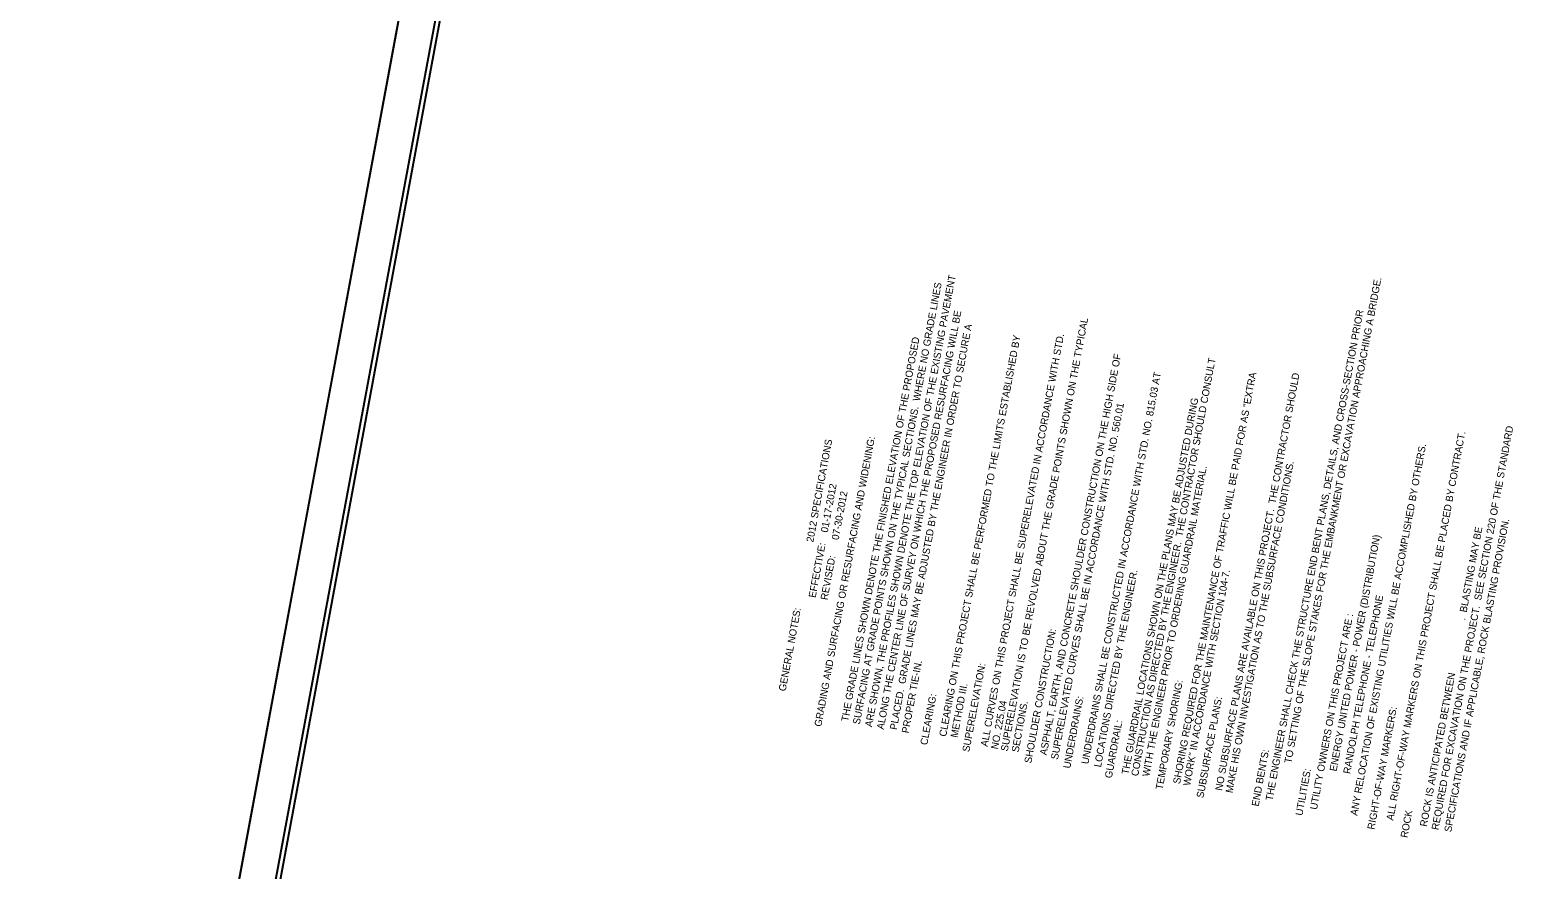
# Model space of a CAD drawing. Extents: x 1665923 to 1668724, y 690926 to 694920.
# Drawn here: x 1667341 to 1668177, y 693895 to 694361 of the extents above; entities that cross this region are included whole.
import ezdxf

# ---------------------------------------------------------------- set-up
doc = ezdxf.new("R2010")
doc.units = 0
for name, color, linetype in [('Default', 7, 'Continuous'), ('Sheet Cutting Line CELL', 7, 'Continuous'), ('Sheet Plan CELL', 7, 'Continuous'), ('Sheet Plot Border Inside CELL', 7, 'Continuous'), ('Sheet Plot Border Outside CELL', 7, 'Continuous')]:
    doc.layers.add(name, color=color, linetype=linetype)

msp = doc.modelspace()

# ---------------------------------------------------------------- linework, layer by layer
at = {"layer": 'Sheet Cutting Line CELL'}
msp.add_line((1667647.87, 694920.43), (1667340.61, 693265.21), dxfattribs=at)
at = {"layer": 'Sheet Plan CELL'}
msp.add_lwpolyline([(1667666.89, 694899.61), (1667393.12, 693424.81), (1668425.49, 693233.17), (1668699.25, 694707.98)], close=True, dxfattribs=at)
at = {"layer": 'Sheet Plot Border Inside CELL'}
msp.add_lwpolyline([(1668399.93, 693081.79), (1668703.99, 694719.81), (1667666.71, 694912.36), (1667362.65, 693274.34)], close=True, dxfattribs=at)
at = {"layer": 'Sheet Plot Border Outside CELL'}
msp.add_lwpolyline([(1668417.22, 693065.36), (1668724.48, 694720.58), (1667647.87, 694920.43), (1667340.61, 693265.21)], close=True, dxfattribs=at)

# ---------------------------------------------------------------- texts
at = {"layer": 'Default'}
for s, p in [('         SURFACING AT GRADE POINTS SHOWN ON THE TYPICAL SECTIONS.  WHERE NO GRADE LINES ', (1667798.61, 693961.96)), ('         ARE SHOWN, THE PROFILES SHOWN DENOTE THE TOP ELEVATION OF THE EXISTING PAVEMENT ', (1667805.38, 693960.55)), ('TO SETTING OF THE SLOPE STAKES FOR THE EMBANKMENT OR EXCAVATION APPROACHING A BRIDGE.  ', (1668040.56, 693953.53)), ('         ALONG THE CENTER LINE OF SURVEY ON WHICH THE PROPOSED RESURFACING WILL BE ', (1667811.9, 693959.19)), ('         THE ENGINEER SHALL CHECK THE STRUCTURE END BENT PLANS, DETAILS, AND CROSS-SECTION PRIOR', (1668027.7, 693919.6)), ('         PLACED.  GRADE LINES MAY BE ADJUSTED BY THE ENGINEER IN ORDER TO SECURE A ', (1667819.16, 693958.97)), ('         SUPERELEVATION IS TO BE REVOLVED ABOUT THE GRADE POINTS SHOWN ON THE TYPICAL ', (1667880.73, 693947.03)), ('         THE GRADE LINES SHOWN DENOTE THE FINISHED ELEVATION OF THE PROPOSED ', (1667792.21, 693963.55)), ('         CLEARING ON THIS PROJECT SHALL BE PERFORMED TO THE LIMITS ESTABLISHED BY ', (1667846.53, 693955.2)), ('         ALL CURVES ON THIS PROJECT SHALL BE SUPERELEVATED IN ACCORDANCE WITH STD. ', (1667869.55, 693949.66)), ('         ASPHALT, EARTH, AND CONCRETE SHOULDER CONSTRUCTION ON THE HIGH SIDE OF', (1667902.35, 693944.9)), ('         CONSTRUCTION AS DIRECTED BY THE ENGINEER.  THE CONTRACTOR SHOULD CONSULT', (1667953.1, 693933.25)), ('         UNDERDRAINS SHALL BE CONSTRUCTED IN ACCORDANCE WITH STD. NO. 815.03 AT ', (1667925.48, 693939.92)), ('         SHORING REQUIRED FOR THE MAINTENANCE OF TRAFFIC WILL BE PAID FOR AS "EXTRA ', (1667976.35, 693928.92)), ('         NO SUBSURFACE PLANS ARE AVAILABLE ON THIS PROJECT.  THE CONTRACTOR SHOULD ', (1667999.72, 693925.19)), ('         SUPERELEVATED CURVES SHALL BE IN ACCORDANCE WITH STD. NO. 560.01', (1667908.57, 693942.44)), ('         THE GUARDRAIL LOCATIONS SHOWN ON THE PLANS MAY BE ADJUSTED DURING ', (1667947.79, 693934.19)), ('GRADING AND SURFACING OR RESURFACING AND WIDENING:  ', (1667779.7, 693973.87)), ('         ALL RIGHT-OF-WAY MARKERS ON THIS PROJECT SHALL BE PLACED BY CONTRACT.  ', (1668094.73, 693908.68)), ('        REQUIRED FOR EXCAVATION ON THE PROJECT.  SEE SECTION 220 OF THE STANDARD', (1668120.06, 693904.85)), ('GENERAL NOTES:                         2012 SPECIFICATIONS', (1667759.9, 693993.55)), ('         ANY RELOCATION OF EXISTING UTILITIES WILL BE ACCOMPLISHED BY OTHERS.  ', (1668074.7, 693911.38)), ('         WITH THE ENGINEER PRIOR TO ORDERING GUARDRAIL MATERIAL.', (1667959.3, 693933.04)), ('         MAKE HIS OWN INVESTIGATION AS TO THE SUBSURFACE CONDITIONS.  ', (1668005.49, 693923.91)), ('                                       EFFECTIVE:    01-17-2012', (1667765.95, 693988.43)), ('                                       REVISED:      07-30-2012', (1667772.55, 693987.19)), ('        ROCK IS ANTICIPATED BETWEEN                    .  BLASTING MAY BE', (1668113.61, 693906.7)), ('        SPECIFICATIONS AND IF APPLICABLE, ROCK BLASTING PROVISION.', (1668127.15, 693903.68)), ('ENERGY UNITED POWER - POWER (DISTRIBUTION)', (1668065.66, 693949.09)), ('         LOCATIONS DIRECTED BY THE ENGINEER.  ', (1667932.49, 693938.21)), ('         WORK" IN ACCORDANCE WITH SECTION 104-7.  ', (1667981.92, 693927.93)), ('RANDOLPH TELEPHONE - TELEPHONE', (1668073.22, 693947.68)), ('         UTILITY OWNERS ON THIS PROJECT ARE :', (1668052.33, 693914.67)), ('SHOULDER CONSTRUCTION:  ', (1667896.26, 693953.58)), ('         PROPER TIE-IN.  ', (1667825.76, 693957.09)), ('SUPERELEVATION:  ', (1667861.83, 693959.86)), ('         METHOD III.', (1667852.87, 693954.64)), ('TEMPORARY SHORING:  ', (1667969.12, 693938.9)), ('CLEARING:  ', (1667838.48, 693963.67)), ('         NO. 225.04', (1667875.29, 693948.19)), ('         SECTIONS.  ', (1667886.74, 693946.53)), ('UNDERDRAINS:  ', (1667917.85, 693950.68)), ('SUBSURFACE PLANS:  ', (1667991.79, 693934.32)), ('RIGHT-OF-WAY MARKERS:  ', (1668086.62, 693916.77)), ('GUARDRAIL:  ', (1667940.9, 693945.27)), ('END BENTS:  ', (1668022.4, 693929.62)), ('UTILITIES:  ', (1668046.71, 693924.49)), ('ROCK', (1668105.01, 693912.2))]:
    msp.add_text(s, height=4, rotation=79.48395, dxfattribs=at).set_placement(p)

doc.saveas('drawing.dxf')
